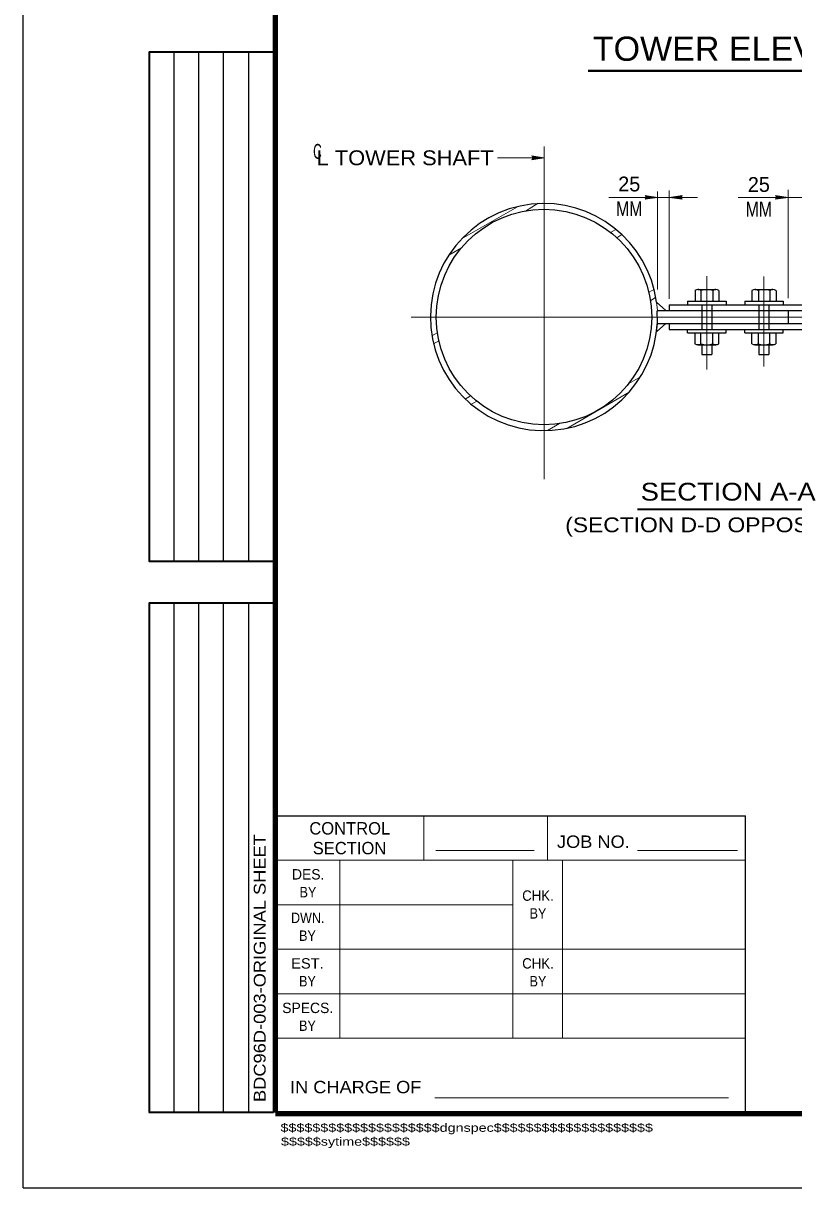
# Model space of a CAD drawing. Extents: x 312601.858 to 312602.699, y 144420.109 to 144420.704.
# Drawn here: x 312601.8578 to 312602.0136, y 144420.1095 to 144420.3449 of the extents above; entities that cross this region are included whole.
import ezdxf
from ezdxf.enums import TextEntityAlignment as Align

# ---------------------------------------------------------------- set-up
doc = ezdxf.new("R2010")
doc.units = 0
doc.header["$LTSCALE"] = 0.0012
doc.linetypes.add('DOT_DASHED', pattern=[7.7, 5, -1.2, 0.3, -1.2])
doc.linetypes.add('LONG_DASHED', pattern=[7.5, 6, -1.5])
for name, color, linetype, lineweight in [('1', 7, 'Continuous', 25), ('2', 7, 'Continuous', 13), ('39', 7, 'Continuous', 13), ('60', 7, 'Continuous', 25), ('9', 7, 'Continuous', 13)]:
    doc.layers.add(name, color=color, linetype=linetype, lineweight=lineweight)

msp = doc.modelspace()

# ---------------------------------------------------------------- hatches: boundary and pattern name
at = {"layer": '39'}
for points in [[(312601.9608, 144420.3177), (312601.9606, 144420.3181), (312601.9631, 144420.3177), (312601.9606, 144420.3173)], [(312601.9837, 144420.3097), (312601.9835, 144420.3101), (312601.986, 144420.3097), (312601.9835, 144420.3093)], [(312601.9907, 144420.3097), (312601.991, 144420.3093), (312601.9884, 144420.3097), (312601.991, 144420.3101)], [(312602.0101, 144420.3097), (312602.0099, 144420.3101), (312602.0124, 144420.3097), (312602.0099, 144420.3093)], [(312602.0101, 144420.3097), (312602.0099, 144420.3101), (312602.0124, 144420.3097), (312602.0099, 144420.3093)]]:
    msp.add_hatch(color=256, dxfattribs=at).paths.add_polyline_path(points)

# ---------------------------------------------------------------- linework, layer by layer
at = {"layer": '1', "lineweight": 13}
for p, q in [((312601.9631, 144420.32), (312601.9631, 144420.313)), ((312601.9631, 144420.3177), (312601.9537, 144420.3177)), ((312601.986, 144420.2911), (312601.986, 144420.3109)), ((312601.9884, 144420.3111), (312601.9884, 144420.2892)), ((312601.9884, 144420.3097), (312601.9941, 144420.3097)), ((312602.0023, 144420.3097), (312602.0124, 144420.3097)), ((312602.0124, 144420.3112), (312602.0124, 144420.2893)), ((312601.9464, 144420.3013), (312601.9577, 144420.3078)), ((312601.9593, 144420.3069), (312601.9619, 144420.3085)), ((312601.9765, 144420.3026), (312601.9776, 144420.3032)), ((312601.9778, 144420.3015), (312601.9788, 144420.3022)), ((312601.9438, 144420.298), (312601.9464, 144420.2995)), ((312601.9843, 144420.2905), (312601.9853, 144420.2911)), ((312601.9846, 144420.2888), (312601.9857, 144420.2895)), ((312601.9404, 144420.2817), (312601.9416, 144420.2824)), ((312601.9407, 144420.2801), (312601.9418, 144420.2807)), ((312601.9942, 144420.2799), (312601.9978, 144420.2799)), ((312601.9802, 144420.2721), (312601.9826, 144420.2734)), ((312601.9471, 144420.2689), (312601.9482, 144420.2696)), ((312601.9677, 144420.263), (312601.9803, 144420.2703)), ((312601.9484, 144420.2679), (312601.9495, 144420.2685)), ((312601.9638, 144420.2626), (312601.9662, 144420.264))]:
    msp.add_line(p, q, dxfattribs=at)
at = {"layer": '1', "linetype": 'DOT_DASHED', "lineweight": 13}
for p, q in [((312601.9631, 144420.3173), (312601.9631, 144420.2527)), ((312601.996, 144420.2749), (312601.996, 144420.2938)), ((312602.0075, 144420.2755), (312602.0075, 144420.2937)), ((312601.9362, 144420.2855), (312602.0468, 144420.2855))]:
    msp.add_line(p, q, dxfattribs=at)
at = {"layer": '1'}
for p, q in [((312601.9936, 144420.2909), (312601.9936, 144420.2887)), ((312601.9942, 144420.2911), (312601.9978, 144420.2911)), ((312601.9942, 144420.2911), (312601.9978, 144420.2911)), ((312601.9948, 144420.2909), (312601.9948, 144420.2887)), ((312601.9972, 144420.2909), (312601.9972, 144420.2887)), ((312601.9984, 144420.2909), (312601.9984, 144420.2887)), ((312602.0051, 144420.2909), (312602.0051, 144420.2887)), ((312602.0057, 144420.2911), (312602.0093, 144420.2911)), ((312602.0057, 144420.2911), (312602.0093, 144420.2911)), ((312602.0064, 144420.2909), (312602.0064, 144420.2887)), ((312602.0087, 144420.2909), (312602.0087, 144420.2887)), ((312602.01, 144420.2909), (312602.01, 144420.2887)), ((312601.9884, 144420.288), (312602.0235, 144420.288)), ((312601.9884, 144420.288), (312601.9884, 144420.2868)), ((312601.9921, 144420.2887), (312601.9921, 144420.288)), ((312602.0037, 144420.2887), (312602.0037, 144420.288)), ((312601.986, 144420.2868), (312602.0235, 144420.2868)), ((312602.0124, 144420.2868), (312602.0124, 144420.2842)), ((312601.986, 144420.2842), (312602.0235, 144420.2842)), ((312601.9884, 144420.2842), (312601.9884, 144420.283)), ((312601.9921, 144420.2823), (312601.9921, 144420.283)), ((312601.9936, 144420.2801), (312601.9936, 144420.2823)), ((312601.9948, 144420.2801), (312601.9948, 144420.2823)), ((312601.9972, 144420.2801), (312601.9972, 144420.2823)), ((312601.9984, 144420.2801), (312601.9984, 144420.2823)), ((312602.0037, 144420.2823), (312602.0037, 144420.283)), ((312602.0051, 144420.2801), (312602.0051, 144420.2823)), ((312602.0064, 144420.2801), (312602.0064, 144420.2823)), ((312602.0087, 144420.2801), (312602.0087, 144420.2823)), ((312602.01, 144420.2801), (312602.01, 144420.2823)), ((312601.9942, 144420.2799), (312601.9978, 144420.2799)), ((312601.995, 144420.2799), (312601.995, 144420.2779)), ((312601.997, 144420.2799), (312601.997, 144420.2779)), ((312602.0057, 144420.2799), (312602.0093, 144420.2799)), ((312602.0057, 144420.2799), (312602.0093, 144420.2799)), ((312602.0065, 144420.2799), (312602.0065, 144420.2779)), ((312602.0085, 144420.28), (312602.0085, 144420.2779)), ((312601.995, 144420.2779), (312601.997, 144420.2779)), ((312602.0065, 144420.2779), (312602.0085, 144420.2779))]:
    msp.add_line(p, q, dxfattribs=at)
at = {"layer": '1', "linetype": 'LONG_DASHED'}
for p, q in [((312601.995, 144420.288), (312601.995, 144420.283)), ((312601.997, 144420.288), (312601.997, 144420.283)), ((312602.0065, 144420.288), (312602.0065, 144420.283)), ((312602.0085, 144420.288), (312602.0085, 144420.283))]:
    msp.add_line(p, q, dxfattribs=at)
at = {"layer": '1', "lineweight": 13}
for points in [[(312601.9762, 144420.3097), (312601.986, 144420.3097), (312601.9884, 144420.3097)], [(312602.0124, 144420.3097), (312602.0151, 144420.3097), (312602.0235, 144420.3097)]]:
    msp.add_lwpolyline(points, dxfattribs=at)
at = {"layer": '1'}
for points in [[(312601.9921, 144420.2887), (312601.9999, 144420.2887), (312601.9999, 144420.288)], [(312602.0037, 144420.2887), (312602.0114, 144420.2887), (312602.0114, 144420.288)], [(312601.9884, 144420.283), (312602.0235, 144420.283), (312602.0235, 144420.2842)], [(312601.9921, 144420.2823), (312601.9999, 144420.2823), (312601.9999, 144420.283)], [(312602.0037, 144420.2823), (312602.0114, 144420.2823), (312602.0114, 144420.283)]]:
    msp.add_lwpolyline(points, dxfattribs=at)
msp.add_circle((312601.96306, 144420.2855), 0.02178, dxfattribs=at)
for centre, radius, start, end in [((312601.96306, 144420.2855), 0.02295, 7.46916, 3.14723), ((312601.9942, 144420.289887), 0.001192, 58.10921, 121.89079), ((312601.994185, 144420.289835), 0.001245, 58.79949, 89.30972), ((312601.996, 144420.287188), 0.003893, 72.50768, 107.49232), ((312601.996, 144420.287188), 0.003893, 72.78254, 107.49232), ((312601.997815, 144420.289835), 0.001245, 90.69028, 121.20051), ((312601.9978, 144420.289887), 0.001192, 58.10921, 121.89079), ((312602.00572, 144420.289887), 0.001192, 58.10921, 121.89079), ((312602.005705, 144420.289835), 0.001245, 58.79949, 89.30972), ((312602.00752, 144420.287188), 0.003893, 72.78254, 107.49232), ((312602.009335, 144420.289835), 0.001245, 90.69028, 121.20051), ((312602.00932, 144420.289887), 0.001192, 58.10921, 121.89079), ((312601.9942, 144420.281113), 0.001192, 238.10921, 301.89079), ((312601.996, 144420.283812), 0.003893, 252.50768, 287.49232), ((312601.9978, 144420.281113), 0.001192, 238.10921, 301.89079), ((312602.00572, 144420.281113), 0.001192, 238.10921, 301.89079), ((312602.005705, 144420.281165), 0.001245, 270.69028, 301.20051), ((312602.00752, 144420.283812), 0.003893, 252.50768, 287.49232), ((312602.00752, 144420.283812), 0.003893, 252.50768, 287.21746), ((312602.00932, 144420.281113), 0.001192, 238.10921, 301.89079), ((312602.009335, 144420.281165), 0.001245, 238.79949, 269.30972)]:
    msp.add_arc(centre, radius, start, end, dxfattribs=at)
at = {"layer": '1', "lineweight": 13}
for centre, radius, start, end in [((312602.00752, 144420.287188), 0.003893, 72.50768, 107.49232), ((312601.994185, 144420.281165), 0.001245, 270.69028, 301.20051), ((312601.996, 144420.283812), 0.003893, 252.50768, 287.21746), ((312601.997815, 144420.281165), 0.001245, 238.79949, 269.30972)]:
    msp.add_arc(centre, radius, start, end, dxfattribs=at)
at = {"layer": '2', "lineweight": 40}
msp.add_line((312601.972, 144420.3353), (312602.0409, 144420.3353), dxfattribs=at)
at = {"layer": '2', "lineweight": 35}
msp.add_line((312601.982, 144420.2467), (312602.0185, 144420.2467), dxfattribs=at)
at = {"layer": '39', "lineweight": 25}
for p, q in [((312601.8578, 144420.1095), (312601.8578, 144420.7035)), ((312601.9088, 144420.1847), (312602.0038, 144420.1847)), ((312602.0038, 144420.1247), (312602.0038, 144420.1847)), ((312601.8578, 144420.1095), (312602.6988, 144420.1095))]:
    msp.add_line(p, q, dxfattribs=at)
at = {"layer": '39', "lineweight": 158}
for p, q in [((312601.9088, 144420.1247), (312601.9088, 144420.6645)), ((312601.9088, 144420.1245), (312602.6838, 144420.1245))]:
    msp.add_line(p, q, dxfattribs=at)
at = {"layer": '39'}
for p, q in [((312601.9088, 144420.1247), (312601.9088, 144420.1847)), ((312601.9388, 144420.1757), (312601.9388, 144420.1847)), ((312601.9638, 144420.1757), (312601.9638, 144420.1847)), ((312601.9412, 144420.1777), (312601.9611, 144420.1777)), ((312601.982, 144420.1777), (312602.0022, 144420.1777)), ((312601.9088, 144420.1757), (312602.0038, 144420.1757)), ((312601.9218, 144420.1397), (312601.9218, 144420.1757)), ((312601.9568, 144420.1397), (312601.9568, 144420.1757)), ((312601.9668, 144420.1397), (312601.9668, 144420.1757)), ((312601.9088, 144420.1667), (312601.9568, 144420.1667)), ((312601.9088, 144420.1577), (312602.0038, 144420.1577)), ((312601.9088, 144420.1487), (312602.0038, 144420.1487)), ((312601.9088, 144420.1397), (312602.0038, 144420.1397)), ((312601.941, 144420.1277), (312602.0004, 144420.1277)), ((312601.9088, 144420.1247), (312602.0038, 144420.1247))]:
    msp.add_line(p, q, dxfattribs=at)
for points in [[(312601.9608, 144420.3177), (312601.9606, 144420.3181), (312601.9631, 144420.3177), (312601.9606, 144420.3173)], [(312601.9837, 144420.3097), (312601.9835, 144420.3101), (312601.986, 144420.3097), (312601.9835, 144420.3093)], [(312601.9907, 144420.3097), (312601.991, 144420.3093), (312601.9884, 144420.3097), (312601.991, 144420.3101)], [(312602.0101, 144420.3097), (312602.0099, 144420.3101), (312602.0124, 144420.3097), (312602.0099, 144420.3093)], [(312602.0101, 144420.3097), (312602.0099, 144420.3101), (312602.0124, 144420.3097), (312602.0099, 144420.3093)]]:
    msp.add_lwpolyline(points, close=True, dxfattribs=at)
at = {"layer": '60'}
for p, q in [((312601.8883, 144420.2361), (312601.8883, 144420.3391)), ((312601.8933, 144420.2361), (312601.8933, 144420.3391)), ((312601.8983, 144420.2361), (312601.8983, 144420.3391)), ((312601.9034, 144420.2361), (312601.9034, 144420.3391)), ((312601.8883, 144420.1247), (312601.8883, 144420.2277)), ((312601.8933, 144420.1247), (312601.8933, 144420.2277)), ((312601.8983, 144420.1247), (312601.8983, 144420.2277)), ((312601.9034, 144420.1247), (312601.9034, 144420.2277))]:
    msp.add_line(p, q, dxfattribs=at)
at = {"layer": '60', "lineweight": 35}
for points in [[(312601.9084, 144420.2361), (312601.8833, 144420.2361), (312601.8833, 144420.3391), (312601.9084, 144420.3391)], [(312601.9084, 144420.1247), (312601.8833, 144420.1247), (312601.8833, 144420.2277), (312601.9084, 144420.2277)]]:
    msp.add_lwpolyline(points, dxfattribs=at)
at = {"layer": '9'}
for points in [[(312601.9877, 144420.2868), (312601.9858, 144420.2885), (312601.986, 144420.2868)], [(312601.986, 144420.2842), (312601.9858, 144420.2825), (312601.9877, 144420.2842)]]:
    msp.add_lwpolyline(points, close=True, dxfattribs=at)

# ---------------------------------------------------------------- texts
at = {"layer": '1'}
for s, height, p in [('CONTROL', 0.0025, (312601.9238, 144420.1809)), ('SECTION', 0.0025, (312601.92375, 144420.1769)), ('DES.', 0.0021, (312601.9154, 144420.1718)), ('SPECS.', 0.0021, (312601.9153, 144420.1448))]:
    msp.add_text(s, height=height, dxfattribs=at).set_placement(p, align=Align.CENTER)
for s, height, width, p in [('JOB NO.', 0.0025, 1.1, (312601.97305, 144420.1782)), ('BY', 0.0021, 0.9, (312601.91535, 144420.1682)), ('CHK.', 0.0021, 0.95, (312601.96185, 144420.1675)), ('BY', 0.0021, 0.9, (312601.96185, 144420.1639)), ('DWN.', 0.0021, 0.9, (312601.9153, 144420.163)), ('BY', 0.0021, 0.9, (312601.91525, 144420.1594)), ('EST.', 0.0021, 1.05, (312601.91525, 144420.1538)), ('CHK.', 0.0021, 0.95, (312601.96185, 144420.1538)), ('BY', 0.0021, 0.9, (312601.91525, 144420.1502)), ('BY', 0.0021, 0.9, (312601.96185, 144420.1502)), ('BY', 0.0021, 0.9, (312601.91525, 144420.1412)), ('IN CHARGE OF', 0.0025, 1.1, (312601.925, 144420.1286))]:
    msp.add_text(s, height=height, dxfattribs=dict(at, width=width)).set_placement(p, align=Align.CENTER)
at = {"layer": '2'}
for s, height, width, p in [('TOWER ELEVATION', 0.0049, 1.05, (312602.006, 144420.3373)), ('MM', 0.003, 0.8, (312601.9803, 144420.3059)), ('MM', 0.003, 0.8, (312602.0065, 144420.3058)), ('SECTION A-A', 0.0036, 1.15, (312602.0003, 144420.2484)), ('(SECTION D-D OPPOSITE HAND)', 0.003, 1.15, (312602.0035, 144420.242))]:
    msp.add_text(s, height=height, dxfattribs=dict(at, width=width)).set_placement(p, align=Align.CENTER)
for s, height, width, p in [('C', 0.003, 0.6, (312601.9164, 144420.3175)), ('L TOWER SHAFT', 0.003, 1.1, (312601.9171, 144420.3162)), ('$$$$$$$$$$$$$$$$$$$$dgnspec$$$$$$$$$$$$$$$$$$$$', 0.001664, 1.3, (312601.9098, 144420.1208)), ('$$$$$sytime$$$$$$', 0.001664, 1.3, (312601.9099, 144420.118))]:
    msp.add_text(s, height=height, dxfattribs=dict(at, width=width)).set_placement(p)
for p in [(312601.9803, 144420.3109), (312602.0065, 144420.3108)]:
    msp.add_text('25', height=0.003, dxfattribs=at).set_placement(p, align=Align.CENTER)
at = {"layer": '2', "width": 1.15}
msp.add_text('BDC96D-003-ORIGINAL SHEET', height=0.0024, rotation=90, dxfattribs=at).set_placement((312601.9068, 144420.1539), align=Align.CENTER)

doc.saveas('drawing.dxf')
